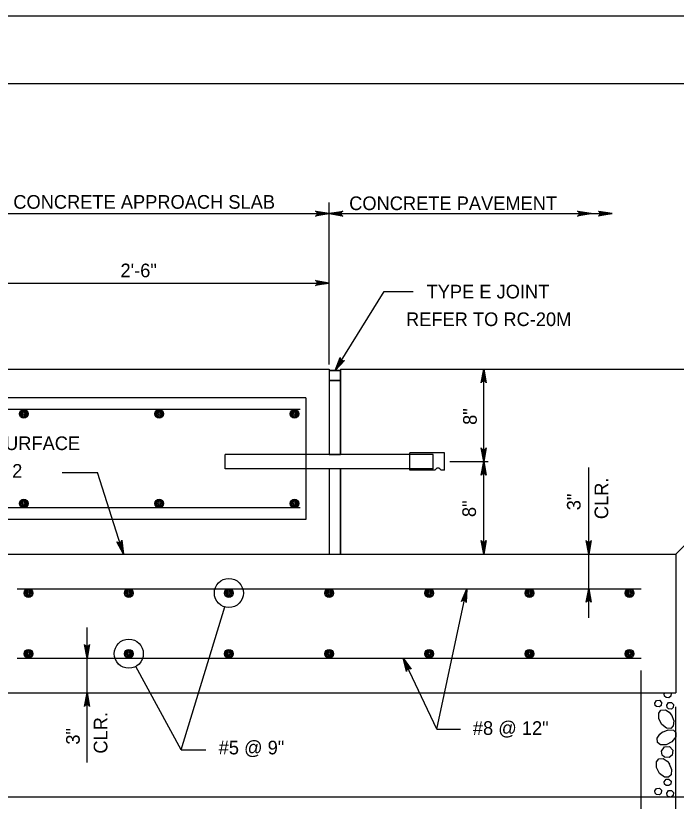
# Model space of a CAD drawing. Extents: x 638079 to 640019, y 297691 to 298879.
# Drawn here: x 639654.7 to 639799.9, y 298706.6 to 298879.2 of the extents above; entities that cross this region are included whole.
import ezdxf

# ---------------------------------------------------------------- set-up
doc = ezdxf.new("R2010")
doc.units = 0
doc.layers.add('1', color=7, linetype='Continuous')
doc.layers.add('PLT-BNDY', color=7, linetype='Continuous')

msp = doc.modelspace()

# ---------------------------------------------------------------- linework, layer by layer
at = {"layer": '1'}
for p, q in [((639723.61, 298802.57), (639723.61, 298838.21)), ((639644.85, 298835.73), (639723.61, 298835.73)), ((639723.61, 298835.73), (639785.78, 298835.73)), ((639647.41, 298820.49), (639723.61, 298820.49)), ((639724.93, 298801.26), (639735.73, 298818.6)), ((639735.73, 298818.6), (639742.06, 298818.6)), ((639581.26, 298801.58), (639723.61, 298801.58)), ((639723.61, 298801.58), (639723.61, 298783.07)), ((639726.14, 298801.58), (639875.1, 298801.58)), ((639726.14, 298801.58), (639726.14, 298782.84)), ((639757.6, 298760.94), (639757.6, 298801.58)), ((639723.61, 298801.26), (639726.14, 298801.26)), ((639723.61, 298799.04), (639726.14, 298799.04)), ((639718.53, 298795.23), (639634.71, 298795.23)), ((639718.53, 298795.23), (639718.53, 298768.56)), ((639717.26, 298792.69), (639633.44, 298792.69)), ((639700.75, 298779.67), (639700.75, 298782.84)), ((639746.47, 298782.84), (639700.75, 298782.84)), ((639749, 298783.15), (639741.38, 298783.15)), ((639741.38, 298782.84), (639741.38, 298783.15)), ((639741.38, 298779.67), (639741.38, 298782.84)), ((639746.47, 298779.67), (639746.47, 298782.84)), ((639749, 298779.36), (639749, 298783.15)), ((639750.14, 298781.26), (639758.57, 298781.26)), ((639799.81, 298760.94), (639820.12, 298781.25)), ((639746.47, 298779.67), (639700.75, 298779.67)), ((639723.61, 298779.67), (639723.61, 298760.94)), ((639726.14, 298779.67), (639726.14, 298760.94)), ((639741.38, 298779.36), (639741.38, 298779.67)), ((639746.87, 298779.36), (639741.38, 298779.36)), ((639749, 298779.36), (639748.16, 298779.36)), ((639780.66, 298746.9), (639780.66, 298779.95)), ((639664.96, 298778.84), (639672.68, 298778.84)), ((639678.41, 298760.94), (639672.68, 298778.84)), ((639717.26, 298771.1), (639633.44, 298771.1)), ((639718.53, 298768.56), (639634.71, 298768.56)), ((639581.26, 298760.94), (639723.61, 298760.94)), ((639647.41, 298760.94), (639799.81, 298760.94)), ((639799.81, 298760.94), (639799.81, 298730.46)), ((639655.03, 298753.32), (639792.19, 298753.32)), ((639747.3, 298722.48), (639753.84, 298753.32)), ((639701.59, 298752.37), (639701.59, 298752.37)), ((639691.1, 298717.94), (639700.66, 298749.3)), ((639670.41, 298715.15), (639670.41, 298744.79)), ((639655.03, 298738.08), (639792.19, 298738.08)), ((639679.58, 298739.03), (639679.58, 298739.03)), ((639747.3, 298722.48), (639739.85, 298738.08)), ((639691.1, 298717.94), (639681.12, 298736.22)), ((639792.19, 298694.87), (639792.19, 298735.38)), ((639647.41, 298730.46), (639799.81, 298730.46)), ((639799.81, 298684.62), (639799.81, 298727.36)), ((639747.3, 298722.48), (639752.5, 298722.48)), ((639691.1, 298717.94), (639696.53, 298717.94)), ((639632.17, 298707.6), (639815.05, 298707.6))]:
    msp.add_line(p, q, dxfattribs=at)
for points in [[(639940.03, 298300.23), (639940.03, 298864.23), (639154.03, 298864.23), (639154.03, 298300.23), (639940.03, 298300.23), (639940.03, 298326.59), (639740.03, 298326.59), (639740.03, 298391.26), (639940.03, 298391.26), (639940.03, 298420.23), (639740.03, 298420.23), (639740.03, 298300.23), (639818.83, 298300.23), (639818.83, 298326.59), (639818.83, 298300.23), (639895.83, 298300.23), (639895.83, 298326.59), (639895.83, 298314.27), (639940.03, 298314.27)], [(639723.61, 298835.73), (639720.62, 298835.18), (639720.74, 298835.26), (639720.85, 298835.33), (639720.91, 298835.43), (639720.97, 298835.53), (639720.99, 298835.63), (639721.01, 298835.73), (639720.99, 298835.83), (639720.97, 298835.93), (639720.91, 298836.03), (639720.85, 298836.13), (639720.74, 298836.21), (639720.62, 298836.29), (639723.61, 298835.73), (639720.74, 298836.21), (639720.85, 298836.13), (639723.61, 298835.73), (639720.91, 298836.03), (639720.97, 298835.93), (639723.61, 298835.73), (639720.99, 298835.83), (639721.01, 298835.73), (639723.61, 298835.73), (639720.99, 298835.63), (639720.97, 298835.53), (639723.61, 298835.73), (639720.91, 298835.43), (639720.85, 298835.33), (639723.61, 298835.73), (639720.74, 298835.26)], [(639723.61, 298835.73), (639726.59, 298836.29), (639726.47, 298836.21), (639726.36, 298836.13), (639726.3, 298836.03), (639726.24, 298835.93), (639726.22, 298835.83), (639726.21, 298835.73), (639726.22, 298835.63), (639726.24, 298835.53), (639726.3, 298835.43), (639726.36, 298835.33), (639726.47, 298835.26), (639726.59, 298835.18), (639723.61, 298835.73), (639726.47, 298835.26), (639726.36, 298835.33), (639723.61, 298835.73), (639726.3, 298835.43), (639726.24, 298835.53), (639723.61, 298835.73), (639726.22, 298835.63), (639726.21, 298835.73), (639723.61, 298835.73), (639726.22, 298835.83), (639726.24, 298835.93), (639723.61, 298835.73), (639726.3, 298836.03), (639726.36, 298836.13), (639723.61, 298835.73), (639726.47, 298836.21)], [(639781.21, 298835.73), (639778.22, 298835.18), (639778.34, 298835.26), (639778.45, 298835.33), (639778.51, 298835.43), (639778.57, 298835.53), (639778.59, 298835.63), (639778.61, 298835.73), (639778.59, 298835.83), (639778.57, 298835.93), (639778.51, 298836.03), (639778.45, 298836.13), (639778.34, 298836.21), (639778.22, 298836.29), (639781.21, 298835.73), (639778.34, 298836.21), (639778.45, 298836.13), (639781.21, 298835.73), (639778.51, 298836.03), (639778.57, 298835.93), (639781.21, 298835.73), (639778.59, 298835.83), (639778.61, 298835.73), (639781.21, 298835.73), (639778.59, 298835.63), (639778.57, 298835.53), (639781.21, 298835.73), (639778.51, 298835.43), (639778.45, 298835.33), (639781.21, 298835.73), (639778.34, 298835.26)], [(639785.78, 298835.73), (639782.79, 298835.18), (639782.91, 298835.26), (639783.02, 298835.33), (639783.08, 298835.43), (639783.14, 298835.53), (639783.16, 298835.63), (639783.18, 298835.73), (639783.16, 298835.83), (639783.14, 298835.93), (639783.08, 298836.03), (639783.02, 298836.13), (639782.91, 298836.21), (639782.79, 298836.29), (639785.78, 298835.73), (639782.91, 298836.21), (639783.02, 298836.13), (639785.78, 298835.73), (639783.08, 298836.03), (639783.14, 298835.93), (639785.78, 298835.73), (639783.16, 298835.83), (639783.18, 298835.73), (639785.78, 298835.73), (639783.16, 298835.63), (639783.14, 298835.53), (639785.78, 298835.73), (639783.08, 298835.43), (639783.02, 298835.33), (639785.78, 298835.73), (639782.91, 298835.26)], [(639723.61, 298820.49), (639720.62, 298819.94), (639720.74, 298820.02), (639720.85, 298820.09), (639720.91, 298820.19), (639720.97, 298820.29), (639720.99, 298820.39), (639721.01, 298820.49), (639720.99, 298820.59), (639720.97, 298820.69), (639720.91, 298820.79), (639720.85, 298820.89), (639720.74, 298820.97), (639720.62, 298821.05), (639723.61, 298820.49), (639720.74, 298820.97), (639720.85, 298820.89), (639723.61, 298820.49), (639720.91, 298820.79), (639720.97, 298820.69), (639723.61, 298820.49), (639720.99, 298820.59), (639721.01, 298820.49), (639723.61, 298820.49), (639720.99, 298820.39), (639720.97, 298820.29), (639723.61, 298820.49), (639720.91, 298820.19), (639720.85, 298820.09), (639723.61, 298820.49), (639720.74, 298820.02)], [(639724.93, 298801.26), (639726.04, 298804.09), (639726.05, 298803.81), (639726.16, 298803.6), (639726.31, 298803.47), (639726.5, 298803.39), (639726.73, 298803.38), (639726.99, 298803.49), (639724.93, 298801.26), (639726.73, 298803.38), (639726.5, 298803.39), (639724.93, 298801.26), (639726.31, 298803.47), (639726.16, 298803.6), (639724.93, 298801.26), (639726.05, 298803.81)], [(639757.6, 298801.58), (639758.16, 298798.59), (639758, 298798.82), (639757.8, 298798.94), (639757.6, 298798.98), (639757.4, 298798.94), (639757.2, 298798.82), (639757.04, 298798.59), (639757.6, 298801.58), (639757.2, 298798.82), (639757.4, 298798.94), (639757.6, 298801.58), (639757.6, 298798.98), (639757.8, 298798.94), (639757.6, 298801.58), (639758, 298798.82)], [(639757.6, 298781.26), (639757.04, 298784.24), (639757.2, 298784.01), (639757.4, 298783.89), (639757.6, 298783.86), (639757.8, 298783.89), (639758, 298784.01), (639758.16, 298784.24), (639757.6, 298781.26), (639758, 298784.01), (639757.8, 298783.89), (639757.6, 298781.26), (639757.6, 298783.86), (639757.4, 298783.89), (639757.6, 298781.26), (639757.2, 298784.01)], [(639757.6, 298781.26), (639758.16, 298778.27), (639758, 298778.5), (639757.8, 298778.62), (639757.6, 298778.66), (639757.4, 298778.62), (639757.2, 298778.5), (639757.04, 298778.27), (639757.6, 298781.26), (639757.2, 298778.5), (639757.4, 298778.62), (639757.6, 298781.26), (639757.6, 298778.66), (639757.8, 298778.62), (639757.6, 298781.26), (639758, 298778.5)], [(639678.41, 298760.94), (639676.96, 298763.61), (639677.08, 298763.52), (639677.19, 298763.44), (639677.3, 298763.41), (639677.41, 298763.38), (639677.51, 298763.4), (639677.61, 298763.41), (639677.7, 298763.46), (639677.79, 298763.51), (639677.87, 298763.59), (639677.95, 298763.68), (639677.99, 298763.81), (639678.03, 298763.95), (639678.41, 298760.94), (639677.99, 298763.81), (639677.95, 298763.68), (639678.41, 298760.94), (639677.87, 298763.59), (639677.79, 298763.51), (639678.41, 298760.94), (639677.7, 298763.46), (639677.61, 298763.41), (639678.41, 298760.94), (639677.51, 298763.4), (639677.41, 298763.38), (639678.41, 298760.94), (639677.3, 298763.41), (639677.19, 298763.44), (639678.41, 298760.94), (639677.08, 298763.52)], [(639757.6, 298760.94), (639757.04, 298763.92), (639757.2, 298763.69), (639757.4, 298763.57), (639757.6, 298763.54), (639757.8, 298763.57), (639758, 298763.69), (639758.16, 298763.92), (639757.6, 298760.94), (639758, 298763.69), (639757.8, 298763.57), (639757.6, 298760.94), (639757.6, 298763.54), (639757.4, 298763.57), (639757.6, 298760.94), (639757.2, 298763.69)], [(639780.66, 298760.94), (639780.1, 298763.92), (639780.18, 298763.8), (639780.26, 298763.69), (639780.36, 298763.63), (639780.46, 298763.57), (639780.56, 298763.55), (639780.66, 298763.54), (639780.76, 298763.55), (639780.86, 298763.57), (639780.96, 298763.63), (639781.06, 298763.69), (639781.14, 298763.8), (639781.22, 298763.92), (639780.66, 298760.94), (639781.14, 298763.8), (639781.06, 298763.69), (639780.66, 298760.94), (639780.96, 298763.63), (639780.86, 298763.57), (639780.66, 298760.94), (639780.76, 298763.55), (639780.66, 298763.54), (639780.66, 298760.94), (639780.56, 298763.55), (639780.46, 298763.57), (639780.66, 298760.94), (639780.36, 298763.63), (639780.26, 298763.69), (639780.66, 298760.94), (639780.18, 298763.8)], [(639753.84, 298753.32), (639753.76, 298750.28), (639753.71, 298750.41), (639753.66, 298750.54), (639753.57, 298750.62), (639753.48, 298750.7), (639753.39, 298750.74), (639753.3, 298750.77), (639753.19, 298750.78), (639753.09, 298750.78), (639752.98, 298750.74), (639752.87, 298750.71), (639752.77, 298750.61), (639752.67, 298750.51), (639753.84, 298753.32), (639752.77, 298750.61), (639752.87, 298750.71), (639753.84, 298753.32), (639752.98, 298750.74), (639753.09, 298750.78), (639753.84, 298753.32), (639753.19, 298750.78), (639753.3, 298750.77), (639753.84, 298753.32), (639753.39, 298750.74), (639753.48, 298750.7), (639753.84, 298753.32), (639753.57, 298750.62), (639753.66, 298750.54), (639753.84, 298753.32), (639753.71, 298750.41)], [(639780.66, 298753.32), (639781.22, 298750.33), (639781.14, 298750.45), (639781.06, 298750.56), (639780.96, 298750.62), (639780.86, 298750.68), (639780.76, 298750.7), (639780.66, 298750.72), (639780.56, 298750.7), (639780.46, 298750.68), (639780.36, 298750.62), (639780.26, 298750.56), (639780.18, 298750.45), (639780.1, 298750.33), (639780.66, 298753.32), (639780.18, 298750.45), (639780.26, 298750.56), (639780.66, 298753.32), (639780.36, 298750.62), (639780.46, 298750.68), (639780.66, 298753.32), (639780.56, 298750.7), (639780.66, 298750.72), (639780.66, 298753.32), (639780.76, 298750.7), (639780.86, 298750.68), (639780.66, 298753.32), (639780.96, 298750.62), (639781.06, 298750.56), (639780.66, 298753.32), (639781.14, 298750.45)], [(639670.41, 298738.08), (639669.85, 298741.06), (639669.93, 298740.94), (639670.01, 298740.83), (639670.11, 298740.77), (639670.21, 298740.71), (639670.31, 298740.69), (639670.41, 298740.68), (639670.51, 298740.69), (639670.61, 298740.71), (639670.71, 298740.77), (639670.81, 298740.83), (639670.89, 298740.94), (639670.97, 298741.06), (639670.41, 298738.08), (639670.89, 298740.94), (639670.81, 298740.83), (639670.41, 298738.08), (639670.71, 298740.77), (639670.61, 298740.71), (639670.41, 298738.08), (639670.51, 298740.69), (639670.41, 298740.68), (639670.41, 298738.08), (639670.31, 298740.69), (639670.21, 298740.71), (639670.41, 298738.08), (639670.11, 298740.77), (639670.01, 298740.83), (639670.41, 298738.08), (639669.93, 298740.94)], [(639739.85, 298738.08), (639741.64, 298735.63), (639741.52, 298735.7), (639741.39, 298735.76), (639741.28, 298735.78), (639741.16, 298735.79), (639741.07, 298735.76), (639740.97, 298735.73), (639740.88, 298735.67), (639740.8, 298735.61), (639740.74, 298735.52), (639740.67, 298735.42), (639740.65, 298735.28), (639740.63, 298735.14), (639739.85, 298738.08), (639740.65, 298735.28), (639740.67, 298735.42), (639739.85, 298738.08), (639740.74, 298735.52), (639740.8, 298735.61), (639739.85, 298738.08), (639740.88, 298735.67), (639740.97, 298735.73), (639739.85, 298738.08), (639741.07, 298735.76), (639741.16, 298735.79), (639739.85, 298738.08), (639741.28, 298735.78), (639741.39, 298735.76), (639739.85, 298738.08), (639741.52, 298735.7)], [(639655.27, 298730.45), (639655.28, 298730.46)], [(639670.41, 298730.46), (639670.97, 298727.47), (639670.89, 298727.59), (639670.81, 298727.7), (639670.71, 298727.76), (639670.61, 298727.82), (639670.51, 298727.84), (639670.41, 298727.86), (639670.31, 298727.84), (639670.21, 298727.82), (639670.11, 298727.76), (639670.01, 298727.7), (639669.93, 298727.59), (639669.85, 298727.47), (639670.41, 298730.46), (639669.93, 298727.59), (639670.01, 298727.7), (639670.41, 298730.46), (639670.11, 298727.76), (639670.21, 298727.82), (639670.41, 298730.46), (639670.31, 298727.84), (639670.41, 298727.86), (639670.41, 298730.46), (639670.51, 298727.84), (639670.61, 298727.82), (639670.41, 298730.46), (639670.71, 298727.76), (639670.81, 298727.7), (639670.41, 298730.46), (639670.89, 298727.59)], [(639797.25, 298730.2), (639797.43, 298730.46)], [(639798.65, 298730.46), (639798.75, 298730.35), (639798.68, 298729.7), (639798.29, 298729.37), (639797.65, 298729.41), (639797.35, 298729.7), (639797.25, 298730.2)], [(639795.17, 298728.19), (639795.58, 298728.76), (639796.22, 298728.8), (639796.67, 298728.33), (639796.6, 298727.68), (639796.21, 298727.35), (639795.57, 298727.4), (639795.27, 298727.69), (639795.17, 298728.19)], [(639797.82, 298727.71), (639798.22, 298728.29), (639798.87, 298728.32), (639799.32, 298727.86), (639799.25, 298727.21), (639798.85, 298726.88), (639798.22, 298726.92), (639797.92, 298727.21), (639797.82, 298727.71)], [(639798.84, 298725.58), (639799.34, 298724.32), (639799.24, 298723.17), (639798.71, 298722.62), (639797.78, 298722.64), (639796.71, 298723.47), (639796.07, 298724.76), (639796.05, 298725.97), (639796.53, 298726.65), (639797.5, 298726.72), (639798.36, 298726.16), (639798.87, 298725.53)], [(639796.84, 298721.81), (639798.1, 298722.31), (639799.26, 298722.21), (639799.81, 298721.69), (639799.79, 298720.75), (639798.96, 298719.68), (639797.67, 298719.04), (639796.45, 298719.02), (639795.77, 298719.5), (639795.71, 298720.47), (639796.26, 298721.33), (639796.89, 298721.84)], [(639796.64, 298717.6), (639797.31, 298718.55), (639798.39, 298718.61), (639799.13, 298717.84), (639799.02, 298716.76), (639798.36, 298716.2), (639797.3, 298716.28), (639796.8, 298716.76), (639796.64, 298717.6)], [(639798.35, 298714.85), (639798.85, 298713.59), (639798.75, 298712.43), (639798.23, 298711.88), (639797.29, 298711.9), (639796.22, 298712.74), (639795.58, 298714.02), (639795.56, 298715.24), (639796.04, 298715.92), (639797.01, 298715.99), (639797.88, 298715.43), (639798.38, 298714.8)], [(639797.25, 298710.89), (639797.66, 298711.46), (639798.3, 298711.5), (639798.75, 298711.04), (639798.68, 298710.39), (639798.29, 298710.05), (639797.65, 298710.1), (639797.35, 298710.39), (639797.25, 298710.89)], [(639795.17, 298708.87), (639795.58, 298709.45), (639796.22, 298709.48), (639796.67, 298709.02), (639796.6, 298708.37), (639796.21, 298708.04), (639795.57, 298708.08), (639795.27, 298708.37), (639795.17, 298708.87)], [(639797.82, 298708.4), (639798.22, 298708.97), (639798.87, 298709.01), (639799.32, 298708.54), (639799.25, 298707.89), (639798.89, 298707.6)], [(639798.41, 298707.6), (639798.22, 298707.61), (639797.92, 298707.9), (639797.82, 298708.4)]]:
    msp.add_lwpolyline(points, dxfattribs=at)
for points in [[(639723.61, 298799.04), (639726.14, 298799.04), (639726.14, 298801.26), (639723.61, 298801.26)], [(639723.61, 298782.84), (639726.14, 298782.84), (639726.14, 298799.04), (639723.61, 298799.04)], [(639723.61, 298760.94), (639726.14, 298760.94), (639726.14, 298779.67), (639723.61, 298779.67)]]:
    msp.add_lwpolyline(points, close=True, dxfattribs=at)
for centre, radius in [((639656.49, 298791.74), 0.952), ((639686.26, 298791.74), 0.952), ((639715.99, 298791.74), 0.952), ((639656.49, 298791.74), 0.714), ((639656.49, 298791.74), 0.476), ((639656.49, 298791.74), 0.238), ((639686.26, 298791.74), 0.714), ((639686.26, 298791.74), 0.476), ((639686.26, 298791.74), 0.238), ((639715.99, 298791.74), 0.714), ((639715.99, 298791.74), 0.476), ((639715.99, 298791.74), 0.238), ((639656.49, 298772.05), 0.952), ((639656.49, 298772.05), 0.714), ((639656.49, 298772.05), 0.476), ((639656.49, 298772.05), 0.238), ((639686.26, 298772.05), 0.952), ((639686.26, 298772.05), 0.714), ((639686.26, 298772.05), 0.476), ((639686.26, 298772.05), 0.238), ((639715.99, 298772.05), 0.952), ((639715.99, 298772.05), 0.714), ((639715.99, 298772.05), 0.476), ((639715.99, 298772.05), 0.238), ((639701.59, 298752.37), 3.2), ((639657.56, 298752.37), 0.952), ((639657.56, 298752.37), 0.714), ((639679.58, 298752.37), 0.952), ((639679.58, 298752.37), 0.714), ((639701.59, 298752.37), 0.952), ((639701.59, 298752.37), 0.714), ((639723.61, 298752.37), 0.952), ((639723.61, 298752.37), 0.714), ((639745.62, 298752.37), 0.952), ((639745.62, 298752.37), 0.714), ((639767.63, 298752.37), 0.952), ((639767.63, 298752.37), 0.714), ((639789.65, 298752.37), 0.952), ((639789.65, 298752.37), 0.714), ((639657.56, 298752.37), 0.476), ((639657.56, 298752.37), 0.238), ((639679.58, 298752.37), 0.476), ((639679.58, 298752.37), 0.238), ((639701.59, 298752.37), 0.476), ((639701.59, 298752.37), 0.238), ((639723.61, 298752.37), 0.476), ((639723.61, 298752.37), 0.238), ((639745.62, 298752.37), 0.476), ((639745.62, 298752.37), 0.238), ((639767.63, 298752.37), 0.476), ((639767.63, 298752.37), 0.238), ((639789.65, 298752.37), 0.476), ((639789.65, 298752.37), 0.238), ((639679.58, 298739.03), 3.2), ((639657.56, 298739.03), 0.952), ((639657.56, 298739.03), 0.714), ((639657.56, 298739.03), 0.476), ((639657.56, 298739.03), 0.238), ((639679.58, 298739.03), 0.952), ((639679.58, 298739.03), 0.714), ((639679.58, 298739.03), 0.476), ((639679.58, 298739.03), 0.238), ((639701.59, 298739.03), 0.952), ((639701.59, 298739.03), 0.714), ((639701.59, 298739.03), 0.476), ((639701.59, 298739.03), 0.238), ((639723.61, 298739.03), 0.952), ((639723.61, 298739.03), 0.714), ((639723.61, 298739.03), 0.476), ((639723.61, 298739.03), 0.238), ((639745.62, 298739.03), 0.952), ((639745.62, 298739.03), 0.714), ((639745.62, 298739.03), 0.476), ((639745.62, 298739.03), 0.238), ((639767.63, 298739.03), 0.952), ((639767.63, 298739.03), 0.714), ((639767.63, 298739.03), 0.476), ((639767.63, 298739.03), 0.238), ((639789.65, 298739.03), 0.952), ((639789.65, 298739.03), 0.714), ((639789.65, 298739.03), 0.476), ((639789.65, 298739.03), 0.238)]:
    msp.add_circle(centre, radius, dxfattribs=at)
msp.add_arc((639747.51, 298779.14), 0.682, 18.6629, 161.3371, dxfattribs=at)
at = {"layer": 'PLT-BNDY'}
msp.add_lwpolyline([(639115.03, 298879.23), (639956.03, 298879.23), (639956.03, 298285.23), (639115.03, 298285.23)], close=True, dxfattribs=at)

# ---------------------------------------------------------------- texts
at = {"layer": '1'}
for s, p in [('CONCRETE APPROACH SLAB', (639654.21, 298836.81)), ('CONCRETE PAVEMENT', (639728.02, 298836.51)), ('2\'-6"', (639677.76, 298821.75)), ('TYPE E JOINT', (639745.03, 298817.1)), ('REFER TO RC-20M', (639740.51, 298811.03)), ('SLIDING SURFACE', (639632.56, 298783.78)), ('SEE NOTE 2', (639632.56, 298777.71)), ('#8 @ 12"', (639755.2, 298721.2)), ('#5 @ 9"', (639699.34, 298716.91))]:
    msp.add_text(s, height=3, dxfattribs=at).set_placement(p)
for s, p in [('8"', (639756.06, 298789.31)), ('CLR.', (639784.95, 298768.6)), ('3"', (639778.88, 298770.56)), ('8"', (639755.89, 298769.06)), ('CLR.', (639674.88, 298717.08)), ('3"', (639668.81, 298719.04))]:
    msp.add_text(s, height=3, rotation=90, dxfattribs=at).set_placement(p)

doc.saveas('drawing.dxf')
